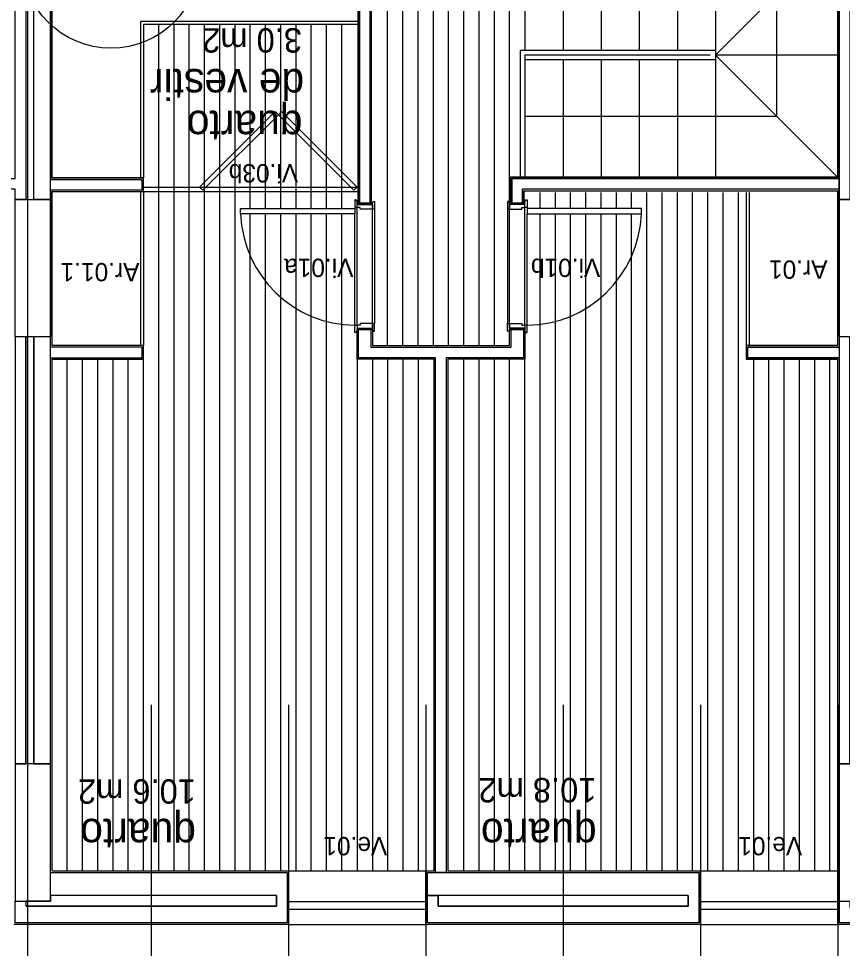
# Model space of a CAD drawing. Extents: x 1278 to 1356, y -253.7 to -224.
# Drawn here: x 1334.62 to 1340.02, y -247.08 to -240.98 of the extents above; entities that cross this region are included whole.
import ezdxf

# ---------------------------------------------------------------- set-up
doc = ezdxf.new("R2010")
doc.units = 0
for name, color, linetype in [('Level 1', 7, 'Continuous'), ('Level 10', 7, 'Continuous'), ('Level 13', 7, 'Continuous'), ('Level 2', 7, 'Continuous'), ('Level 4', 7, 'Continuous'), ('Level 40', 7, 'Continuous'), ('Level 60', 7, 'Continuous'), ('Level 65', 7, 'Continuous'), ('Level 66', 7, 'Continuous'), ('Level 67', 7, 'Continuous'), ('Level 69', 7, 'Continuous'), ('Level 70', 7, 'Continuous'), ('Level 93', 7, 'Continuous')]:
    doc.layers.add(name, color=color, linetype=linetype)

msp = doc.modelspace()

# ---------------------------------------------------------------- linework, layer by layer
at = {"layer": 'Level 1'}
for p, q in [((1334.8333, -246.584), (1334.8332, -232.2657)), ((1334.6725, -236.7713), (1334.6725, -242.1713)), ((1334.7233, -242.1713), (1334.7233, -236.7713)), ((1336.8583, -240.414), (1336.8583, -242.194)), ((1336.9283, -242.194), (1336.9283, -240.414)), ((1340.0033, -240.414), (1340.0033, -242.034)), ((1335.4333, -242.109), (1335.4333, -242.039)), ((1340.0033, -242.034), (1337.8583, -242.034)), ((1337.8583, -242.034), (1337.8583, -242.194)), ((1337.9283, -242.194), (1337.9283, -242.104)), ((1340.0033, -242.104), (1337.9283, -242.104)), ((1340.0033, -242.104), (1340.0033, -243.139)), ((1340.0033, -242.104), (1340.0033, -243.139)), ((1336.8433, -242.194), (1336.9433, -242.194)), ((1337.9383, -242.194), (1337.8487, -242.194)), ((1336.8433, -243.219), (1336.8433, -243.024)), ((1336.8433, -243.024), (1336.9433, -243.024)), ((1336.8533, -243.209), (1336.8533, -243.024)), ((1336.9333, -243.024), (1336.9333, -243.139)), ((1337.9433, -243.024), (1337.8433, -243.024)), ((1337.8533, -243.139), (1337.8533, -243.024)), ((1337.9333, -243.024), (1337.9333, -243.209)), ((1334.6725, -243.0713), (1334.6725, -245.8713)), ((1334.7233, -245.8713), (1334.7233, -243.0713)), ((1334.8333, -243.139), (1334.8333, -243.134)), ((1335.4333, -243.139), (1334.8333, -243.139)), ((1335.4333, -243.209), (1335.4333, -243.139)), ((1336.9333, -243.139), (1337.8533, -243.139)), ((1339.4033, -243.139), (1339.4033, -243.209)), ((1340.0033, -243.139), (1339.4033, -243.139)), ((1334.8333, -243.209), (1335.4333, -243.209)), ((1337.3583, -243.209), (1336.8533, -243.209)), ((1337.3583, -246.584), (1337.3583, -243.209)), ((1337.4283, -243.209), (1337.4283, -246.584)), ((1337.9333, -243.209), (1337.4283, -243.209)), ((1339.4033, -243.209), (1340.0033, -243.209)), ((1340.0033, -243.209), (1340.0033, -246.914)), ((1334.8325, -246.584), (1336.384, -246.584)), ((1336.384, -246.584), (1336.384, -246.914)), ((1337.304, -246.914), (1337.304, -246.584)), ((1337.304, -246.584), (1339.0833, -246.584)), ((1339.0833, -246.584), (1339.0833, -246.914)), ((1336.314, -246.734), (1336.314, -246.804)), ((1337.374, -246.804), (1337.374, -246.734)), ((1339.0133, -246.734), (1339.0133, -246.804)), ((1334.6725, -246.7713), (1334.6725, -246.804)), ((1336.384, -246.914), (1334.6025, -246.914)), ((1339.0833, -246.914), (1337.304, -246.914)), ((1341.784, -246.914), (1340.0033, -246.914))]:
    msp.add_line(p, q, dxfattribs=at)
at = {"layer": 'Level 10'}
for p, q in [((1337.0433, -243.129), (1337.0433, -240.439)), ((1337.1433, -243.129), (1337.1433, -240.424)), ((1337.2433, -243.129), (1337.2433, -240.424)), ((1337.3433, -243.129), (1337.3433, -240.424)), ((1337.4433, -243.129), (1337.4433, -240.424)), ((1337.5433, -243.129), (1337.5433, -240.424)), ((1337.6433, -243.129), (1337.6433, -240.424)), ((1337.7433, -243.129), (1337.7433, -240.439)), ((1337.8433, -242.194), (1337.8433, -240.424)), ((1335.5433, -246.574), (1335.5433, -241.024)), ((1335.6433, -246.574), (1335.6433, -241.024)), ((1335.7433, -246.574), (1335.7433, -241.024)), ((1335.8433, -246.574), (1335.8433, -241.024)), ((1335.9433, -246.574), (1335.9433, -241.024)), ((1336.0433, -246.574), (1336.0433, -241.024)), ((1336.1433, -242.229), (1336.1433, -241.024)), ((1336.2433, -242.229), (1336.2433, -241.024)), ((1336.3433, -242.229), (1336.3433, -241.024)), ((1336.4433, -242.229), (1336.4433, -241.024)), ((1336.5433, -242.229), (1336.5433, -241.024)), ((1336.6433, -242.229), (1336.6433, -241.024)), ((1336.7433, -242.229), (1336.7433, -241.024)), ((1338.0433, -242.229), (1338.0433, -242.124)), ((1338.1433, -242.229), (1338.1433, -242.124)), ((1338.2433, -242.229), (1338.2433, -242.124)), ((1338.3433, -242.229), (1338.3433, -242.124)), ((1338.4433, -242.229), (1338.4433, -242.124)), ((1338.5433, -242.229), (1338.5433, -242.124)), ((1338.6433, -242.229), (1338.6433, -242.124)), ((1338.7433, -246.574), (1338.7433, -242.124)), ((1338.8433, -246.574), (1338.8433, -242.124)), ((1338.9433, -246.574), (1338.9433, -242.124)), ((1339.0433, -246.574), (1339.0433, -242.124)), ((1339.1433, -246.574), (1339.1433, -242.124)), ((1339.2433, -246.574), (1339.2433, -242.124)), ((1339.3433, -246.574), (1339.3433, -242.124)), ((1336.8433, -242.994), (1336.8433, -242.224)), ((1336.9433, -242.984), (1336.9433, -242.234)), ((1337.8433, -242.984), (1337.8433, -242.234)), ((1337.9433, -242.994), (1337.9433, -242.224)), ((1336.1433, -246.574), (1336.1433, -242.264)), ((1336.2433, -246.574), (1336.2433, -242.264)), ((1336.3433, -246.574), (1336.3433, -242.264)), ((1336.4433, -246.574), (1336.4433, -242.264)), ((1336.5433, -246.574), (1336.5433, -242.264)), ((1336.6433, -246.574), (1336.6433, -242.264)), ((1336.7433, -246.574), (1336.7433, -242.264)), ((1338.0433, -246.574), (1338.0433, -242.264)), ((1338.1433, -246.574), (1338.1433, -242.264)), ((1338.2433, -246.574), (1338.2433, -242.264)), ((1338.3433, -246.574), (1338.3433, -242.264)), ((1338.4433, -246.574), (1338.4433, -242.264)), ((1338.5433, -246.574), (1338.5433, -242.264)), ((1338.6433, -246.574), (1338.6433, -242.264)), ((1334.9433, -246.574), (1334.9433, -243.219)), ((1335.0433, -246.574), (1335.0433, -243.219)), ((1335.1433, -246.574), (1335.1433, -243.219)), ((1335.2433, -246.574), (1335.2433, -243.219)), ((1335.3433, -246.574), (1335.3433, -243.219)), ((1335.4433, -246.574), (1335.4433, -243.219)), ((1336.8433, -243.219), (1336.8433, -246.574)), ((1336.9433, -243.219), (1336.9433, -246.574)), ((1337.0433, -243.219), (1337.0433, -246.574)), ((1337.1433, -243.219), (1337.1433, -246.574)), ((1337.2433, -243.219), (1337.2433, -246.574)), ((1337.5433, -246.574), (1337.5433, -243.219)), ((1337.6433, -246.574), (1337.6433, -243.219)), ((1337.7433, -246.574), (1337.7433, -243.219)), ((1337.8433, -246.574), (1337.8433, -243.219)), ((1337.9433, -246.574), (1337.9433, -243.219)), ((1339.4433, -246.574), (1339.4433, -243.219)), ((1339.5433, -246.574), (1339.5433, -243.219)), ((1339.6433, -246.574), (1339.6433, -243.219)), ((1339.7433, -246.574), (1339.7433, -243.219)), ((1339.8433, -246.574), (1339.8433, -243.219)), ((1339.9433, -246.574), (1339.9433, -243.219))]:
    msp.add_line(p, q, dxfattribs=at)
at = {"layer": 'Level 13'}
for p, q in [((1336.8433, -241.004), (1335.4233, -241.004)), ((1335.4233, -241.004), (1335.4233, -242.029)), ((1336.8433, -241.024), (1335.4433, -241.024)), ((1335.4433, -241.024), (1335.4433, -242.029)), ((1335.8109, -242.089), (1336.3059, -241.594)), ((1335.8321, -242.1102), (1336.3271, -241.6152)), ((1336.3059, -241.594), (1336.3271, -241.6152)), ((1336.3483, -241.594), (1336.3271, -241.6152)), ((1336.8221, -242.1102), (1336.3271, -241.6152)), ((1336.8433, -242.089), (1336.3483, -241.594)), ((1335.8109, -242.089), (1335.8321, -242.1102)), ((1336.8433, -242.089), (1336.8221, -242.1102)), ((1335.4233, -242.119), (1335.4233, -243.129)), ((1335.4433, -242.119), (1335.4433, -243.129)), ((1336.8283, -242.174), (1336.8283, -242.224)), ((1336.8383, -242.174), (1336.8283, -242.174)), ((1336.8383, -242.179), (1336.8383, -242.174)), ((1337.9483, -242.179), (1337.9483, -242.174)), ((1337.9483, -242.174), (1337.9583, -242.174)), ((1337.9583, -242.174), (1337.9583, -242.224)), ((1339.3933, -242.124), (1339.3933, -243.129)), ((1339.4133, -242.124), (1339.4133, -243.129)), ((1336.0783, -242.229), (1336.8283, -242.229)), ((1336.0783, -242.264), (1336.0783, -242.229)), ((1336.8283, -242.224), (1336.8433, -242.224)), ((1336.8283, -242.229), (1336.8283, -242.264)), ((1336.8433, -242.179), (1336.8383, -242.179)), ((1336.8433, -242.224), (1336.8433, -242.179)), ((1336.8433, -242.204), (1336.9433, -242.204)), ((1336.8433, -242.224), (1336.8433, -242.204)), ((1336.8633, -242.224), (1336.8433, -242.224)), ((1336.8633, -242.234), (1336.8633, -242.224)), ((1336.9433, -242.234), (1336.8633, -242.234)), ((1336.9433, -242.234), (1336.9433, -242.189)), ((1336.9433, -242.189), (1336.9483, -242.189)), ((1336.9433, -242.204), (1336.9433, -242.234)), ((1336.9583, -242.234), (1336.9433, -242.234)), ((1336.9483, -242.189), (1336.9483, -242.184)), ((1336.9483, -242.184), (1336.9583, -242.184)), ((1336.9583, -242.184), (1336.9583, -242.234)), ((1337.8283, -242.184), (1337.8283, -242.234)), ((1337.8383, -242.184), (1337.8283, -242.184)), ((1337.8283, -242.234), (1337.8433, -242.234)), ((1337.8383, -242.189), (1337.8383, -242.184)), ((1337.8433, -242.189), (1337.8383, -242.189)), ((1337.8433, -242.234), (1337.8433, -242.189)), ((1337.9433, -242.204), (1337.8433, -242.204)), ((1337.8433, -242.204), (1337.8433, -242.234)), ((1337.8433, -242.234), (1337.9233, -242.234)), ((1337.9233, -242.234), (1337.9233, -242.224)), ((1337.9233, -242.224), (1337.9433, -242.224)), ((1337.9433, -242.224), (1337.9433, -242.179)), ((1337.9433, -242.179), (1337.9483, -242.179)), ((1337.9433, -242.224), (1337.9433, -242.204)), ((1337.9583, -242.224), (1337.9433, -242.224)), ((1338.7083, -242.229), (1337.9583, -242.229)), ((1337.9583, -242.229), (1337.9583, -242.264)), ((1338.7083, -242.264), (1338.7083, -242.229)), ((1336.8283, -242.264), (1336.0783, -242.264)), ((1337.9583, -242.264), (1338.7083, -242.264)), ((1336.8283, -243.044), (1336.8283, -242.994)), ((1336.8283, -242.994), (1336.8433, -242.994)), ((1336.8433, -242.994), (1336.8433, -243.039)), ((1336.8633, -242.994), (1336.8433, -242.994)), ((1336.8433, -242.994), (1336.8433, -243.014)), ((1336.8433, -243.014), (1336.9433, -243.014)), ((1336.9433, -242.984), (1336.8633, -242.984)), ((1336.8633, -242.984), (1336.8633, -242.994)), ((1336.9433, -243.014), (1336.9433, -242.984)), ((1336.9583, -242.984), (1336.9433, -242.984)), ((1336.9433, -242.984), (1336.9433, -243.029)), ((1336.9433, -243.029), (1336.9483, -243.029)), ((1336.9483, -243.029), (1336.9483, -243.034)), ((1336.9583, -243.034), (1336.9583, -242.984)), ((1337.8283, -243.034), (1337.8283, -242.984)), ((1337.8283, -242.984), (1337.8433, -242.984)), ((1337.8433, -243.029), (1337.8383, -243.029)), ((1337.8383, -243.029), (1337.8383, -243.034)), ((1337.8433, -242.984), (1337.8433, -243.029)), ((1337.8433, -243.014), (1337.8433, -242.984)), ((1337.8433, -242.984), (1337.9233, -242.984)), ((1337.9433, -243.014), (1337.8433, -243.014)), ((1337.9233, -242.984), (1337.9233, -242.994)), ((1337.9233, -242.994), (1337.9433, -242.994)), ((1337.9433, -242.994), (1337.9433, -243.014)), ((1337.9583, -242.994), (1337.9433, -242.994)), ((1337.9433, -242.994), (1337.9433, -243.039)), ((1337.9583, -243.044), (1337.9583, -242.994)), ((1336.8383, -243.044), (1336.8283, -243.044)), ((1336.8433, -243.039), (1336.8383, -243.039)), ((1336.8383, -243.039), (1336.8383, -243.044)), ((1336.9483, -243.034), (1336.9583, -243.034)), ((1337.8383, -243.034), (1337.8283, -243.034)), ((1337.9433, -243.039), (1337.9483, -243.039)), ((1337.9483, -243.039), (1337.9483, -243.044)), ((1337.9483, -243.044), (1337.9583, -243.044))]:
    msp.add_line(p, q, dxfattribs=at)
at = {"layer": 'Level 2'}
for p, q in [((1337.9433, -240.424), (1337.9433, -241.194)), ((1338.1933, -240.424), (1338.1933, -241.194)), ((1338.4433, -240.424), (1338.4433, -241.194)), ((1338.6933, -240.424), (1338.6933, -241.194)), ((1338.9433, -240.424), (1338.9433, -241.194)), ((1339.1933, -240.424), (1339.1933, -241.194)), ((1339.1933, -241.224), (1339.9933, -240.424)), ((1339.5933, -240.824), (1339.5933, -241.624)), ((1339.1933, -241.194), (1337.9133, -241.194)), ((1337.9133, -241.194), (1337.9133, -242.024)), ((1339.1933, -241.194), (1339.1933, -241.254)), ((1337.9433, -241.224), (1337.9433, -242.024)), ((1337.9433, -241.224), (1337.9433, -242.024)), ((1339.1933, -241.254), (1337.9433, -241.254)), ((1339.1586, -241.224), (1337.944, -241.224)), ((1338.1933, -241.254), (1338.1933, -242.024)), ((1338.4433, -241.254), (1338.4433, -242.024)), ((1338.6933, -241.254), (1338.6933, -242.024)), ((1338.9433, -241.254), (1338.9433, -242.024)), ((1339.9933, -241.224), (1339.1933, -241.224)), ((1339.1933, -241.224), (1339.9933, -242.024)), ((1339.1933, -241.254), (1339.1933, -242.024)), ((1337.9433, -241.624), (1339.5933, -241.624)), ((1336.394, -246.574), (1337.294, -246.574)), ((1339.0933, -246.574), (1339.9933, -246.574)), ((1336.394, -246.774), (1337.294, -246.774)), ((1339.0933, -246.774), (1339.9933, -246.774)), ((1336.394, -246.824), (1337.294, -246.824)), ((1339.0933, -246.824), (1339.9933, -246.824)), ((1336.394, -246.924), (1337.294, -246.924)), ((1339.0933, -246.924), (1339.9933, -246.924))]:
    msp.add_line(p, q, dxfattribs=at)
at = {"layer": 'Level 4'}
for p, q in [((1335.4433, -242.089), (1336.8433, -242.089)), ((1335.4433, -242.119), (1336.8433, -242.119)), ((1336.9583, -242.234), (1336.9583, -242.984)), ((1337.8283, -242.234), (1337.8283, -242.984)), ((1336.8283, -242.994), (1336.8283, -242.264)), ((1337.9583, -242.994), (1337.9583, -242.264))]:
    msp.add_line(p, q, dxfattribs=at)
for centre, start_param, end_param in [((1336.8283, -242.2308), 1.614288, 3.141593), ((1337.9583, -242.2308), 3.141593, 4.668897)]:
    msp.add_ellipse(centre, major_axis=(0, 0.7632), ratio=0.982661, start_param=start_param, end_param=end_param, dxfattribs=at)
at = {"layer": 'Level 65'}
for p, q in [((1336.8483, -240.424), (1336.8483, -242.194)), ((1336.9383, -242.194), (1336.9383, -240.424)), ((1339.9933, -240.424), (1339.9933, -242.024)), ((1334.8433, -242.029), (1334.8433, -240.684)), ((1335.4433, -242.029), (1334.8433, -242.029)), ((1335.4433, -242.119), (1335.4433, -242.029)), ((1337.8483, -242.024), (1337.8483, -242.194)), ((1339.9933, -242.024), (1337.8483, -242.024)), ((1337.9383, -242.194), (1337.9383, -242.114)), ((1337.9383, -242.114), (1339.9933, -242.114)), ((1339.9933, -242.114), (1339.9933, -243.129)), ((1334.8433, -242.119), (1335.4433, -242.119)), ((1334.8433, -243.129), (1334.8433, -242.119)), ((1336.9433, -243.024), (1336.9433, -243.129)), ((1337.8433, -243.129), (1337.8433, -243.024)), ((1337.9433, -243.024), (1337.9433, -243.219)), ((1335.4433, -243.129), (1334.8433, -243.129)), ((1335.4433, -243.219), (1335.4433, -243.129)), ((1336.9433, -243.129), (1337.8433, -243.129)), ((1339.3933, -243.129), (1339.3933, -243.219)), ((1339.9933, -243.129), (1339.3933, -243.129)), ((1334.8433, -246.574), (1334.8433, -243.219)), ((1334.8433, -243.219), (1335.4433, -243.219)), ((1337.3483, -243.219), (1336.8433, -243.219)), ((1337.3483, -246.574), (1337.3483, -243.219)), ((1337.9433, -243.219), (1337.4383, -243.219)), ((1337.4383, -243.219), (1337.4383, -246.574)), ((1339.3933, -243.219), (1339.9933, -243.219)), ((1339.9933, -243.219), (1339.9933, -246.924)), ((1334.8433, -246.574), (1336.394, -246.574)), ((1336.394, -246.574), (1336.394, -246.924)), ((1337.294, -246.924), (1337.294, -246.574)), ((1337.294, -246.574), (1337.3483, -246.574)), ((1337.4383, -246.574), (1339.0933, -246.574)), ((1339.0933, -246.574), (1339.0933, -246.924)), ((1336.394, -246.924), (1334.5925, -246.924)), ((1339.0933, -246.924), (1337.294, -246.924)), ((1341.794, -246.924), (1339.9933, -246.924))]:
    msp.add_line(p, q, dxfattribs=at)
at = {"layer": 'Level 66'}
for p, q in [((1335.4333, -242.039), (1334.8333, -242.039)), ((1335.4333, -242.109), (1334.8333, -242.109)), ((1336.314, -246.734), (1334.8325, -246.734)), ((1334.8325, -246.734), (1334.8325, -246.7713)), ((1339.0133, -246.734), (1337.374, -246.734)), ((1334.8325, -246.7713), (1334.6725, -246.7713)), ((1336.314, -246.804), (1334.6725, -246.804)), ((1339.0133, -246.804), (1337.374, -246.804))]:
    msp.add_line(p, q, dxfattribs=at)
for points in [[(1334.8325, -243.0713), (1334.6025, -243.0713), (1334.6025, -242.1713), (1334.8325, -242.1713)], [(1340.2333, -243.0713), (1340.0033, -243.0713), (1340.0033, -242.1713), (1340.2333, -242.1713)], [(1334.8325, -245.8713), (1334.6025, -245.8713), (1334.6025, -246.7713), (1334.8325, -246.7713)], [(1340.2333, -245.8713), (1340.0033, -245.8713), (1340.0033, -246.7713), (1340.2333, -246.7713)]]:
    msp.add_lwpolyline(points, close=True, dxfattribs=at)
at = {"layer": 'Level 67'}
for points in [[(1334.6725, -242.1713), (1334.6025, -242.1713), (1334.6025, -242.104), (1332.5275, -242.104), (1332.5275, -242.194), (1332.4575, -242.194), (1332.4575, -242.034), (1334.6025, -242.034), (1334.6025, -236.7713), (1334.6725, -236.7713)], [(1335.4333, -242.039), (1335.4333, -242.109), (1334.8333, -242.109), (1334.8333, -242.1713), (1334.7233, -242.1713), (1334.7233, -236.7713), (1334.8325, -236.7713), (1334.8333, -242.039)], [(1340.0733, -242.1713), (1340.0033, -242.1713), (1340.0033, -236.7713), (1340.0733, -236.7713)], [(1336.9283, -240.414), (1336.9283, -242.194), (1336.8583, -242.194), (1336.8583, -240.414)], [(1340.0033, -242.104), (1337.9283, -242.104), (1337.9283, -242.194), (1337.8583, -242.194), (1337.8583, -242.034), (1340.0033, -242.034)], [(1337.4283, -246.584), (1337.3583, -246.584), (1337.3583, -243.209), (1336.8533, -243.209), (1336.8533, -243.024), (1336.9333, -243.024), (1336.9333, -243.139), (1337.8533, -243.139), (1337.8533, -243.024), (1337.9333, -243.024), (1337.9333, -243.209), (1337.4283, -243.209)], [(1334.6725, -243.0713), (1334.6025, -243.0713), (1334.6025, -245.8713), (1334.6725, -245.8713)], [(1334.7233, -243.0713), (1334.7233, -245.8713), (1334.8325, -245.8713), (1334.8333, -243.209), (1335.4333, -243.209), (1335.4333, -243.139), (1334.8333, -243.139), (1334.8325, -243.0713)], [(1340.0733, -243.0713), (1340.0033, -243.0713), (1340.0033, -245.8713), (1340.0733, -245.8713)], [(1340.0033, -243.209), (1339.4033, -243.209), (1339.4033, -243.139), (1340.0033, -243.139)], [(1334.8325, -246.584), (1336.384, -246.584), (1336.384, -246.914), (1334.6025, -246.914), (1334.6025, -246.7713), (1334.6725, -246.7713), (1334.6725, -246.804), (1336.314, -246.804), (1336.314, -246.734), (1334.8325, -246.734)], [(1339.0833, -246.914), (1337.304, -246.914), (1337.304, -246.734), (1337.374, -246.734), (1337.374, -246.804), (1339.0133, -246.804), (1339.0133, -246.734), (1337.304, -246.734), (1337.304, -246.584), (1339.0833, -246.584)], [(1341.784, -246.584), (1341.784, -246.914), (1340.0033, -246.914), (1340.0033, -246.7713), (1340.0733, -246.7713), (1340.0733, -246.814), (1341.714, -246.814), (1341.714, -246.734), (1340.2333, -246.734), (1340.2333, -246.584)]]:
    msp.add_lwpolyline(points, close=True, dxfattribs=at)
at = {"layer": 'Level 69'}
msp.add_circle((1335.2301, -240.5951), 0.5842, dxfattribs=at)
at = {"layer": 'Level 70'}
msp.add_line((1334.684, -250.7923), (1334.684, -229.6198), dxfattribs=at)
at = {"layer": 'Level 93'}
for p, q in [((1335.494, -245.4838), (1335.494, -250.4459)), ((1336.394, -245.4838), (1336.394, -250.4459)), ((1337.294, -245.4838), (1337.294, -250.4459)), ((1338.194, -245.4838), (1338.194, -250.4459)), ((1339.094, -245.4838), (1339.094, -250.4459)), ((1339.994, -245.4838), (1339.994, -250.4459))]:
    msp.add_line(p, q, dxfattribs=at)

# ---------------------------------------------------------------- texts
at = {"layer": 'Level 40'}
for s, rotation, p in [('Vi.03b', 180.00001, (1336.4568, -241.939)), ('Ar.01.1', 179.99999, (1335.4168, -242.5872)), ('Vi.01a', 180.00001, (1336.8196, -242.5589)), ('Vi.01b', 180.00001, (1338.4377, -242.5589)), ('Ar.01', 179.99999, (1339.9273, -242.5706)), ('Ve.01', 180.00001, (1337.0412, -246.3511)), ('Ve.01', 180.00001, (1339.7616, -246.3511))]:
    msp.add_text(s, height=0.12, rotation=rotation, dxfattribs=at).set_placement(p)
at = {"layer": 'Level 60'}
for s, height, p in [('3.0 m2', 0.16, (1336.4819, -241.0475)), ('de vestir', 0.2, (1336.4962, -241.3153)), ('de vestir', 0.2, (1336.4962, -241.3153)), ('quarto', 0.2, (1336.4852, -241.5889)), ('10.6 m2', 0.16, (1335.7867, -245.9726)), ('10.8 m2', 0.16, (1338.4124, -245.9642)), ('quarto', 0.2, (1335.7867, -246.232)), ('quarto', 0.2, (1338.4137, -246.232))]:
    msp.add_text(s, height=height, rotation=180, dxfattribs=at).set_placement(p)

doc.saveas('drawing.dxf')
